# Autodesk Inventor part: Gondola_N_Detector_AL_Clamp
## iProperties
Shininess: 64.0
Length Units: 11272
Angle Units: 11279
Time Units: 11290
Mass Units: 11286
Length Display Precision: 3
Angle Display Precision: 2
Compacted: True
Part Number: Gondola_N_Detector_AL_Clamp
Document SubType Name: Modeling
Created: 2004-12
Designer: John Blackburn
Manufacturer: Standard
Standards Organization: Custom
Density: 0.0
Volumn: 0.0
Area: 0.0
PropertySet Name: Model Information
Control State: 0
Master: False
Checked Out: False
Author: John Blackburn
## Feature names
1. Extrusion1
2. Extrusion2
3. Hole1
